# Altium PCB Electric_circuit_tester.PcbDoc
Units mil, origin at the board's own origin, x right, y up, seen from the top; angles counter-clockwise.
Board outline 6043.31 x 4149.61 mil, 2 copper layers (Top Layer, Top, Bottom Layer, Bottom); 15 components, 10 nets, 34 pads, 0 vias.
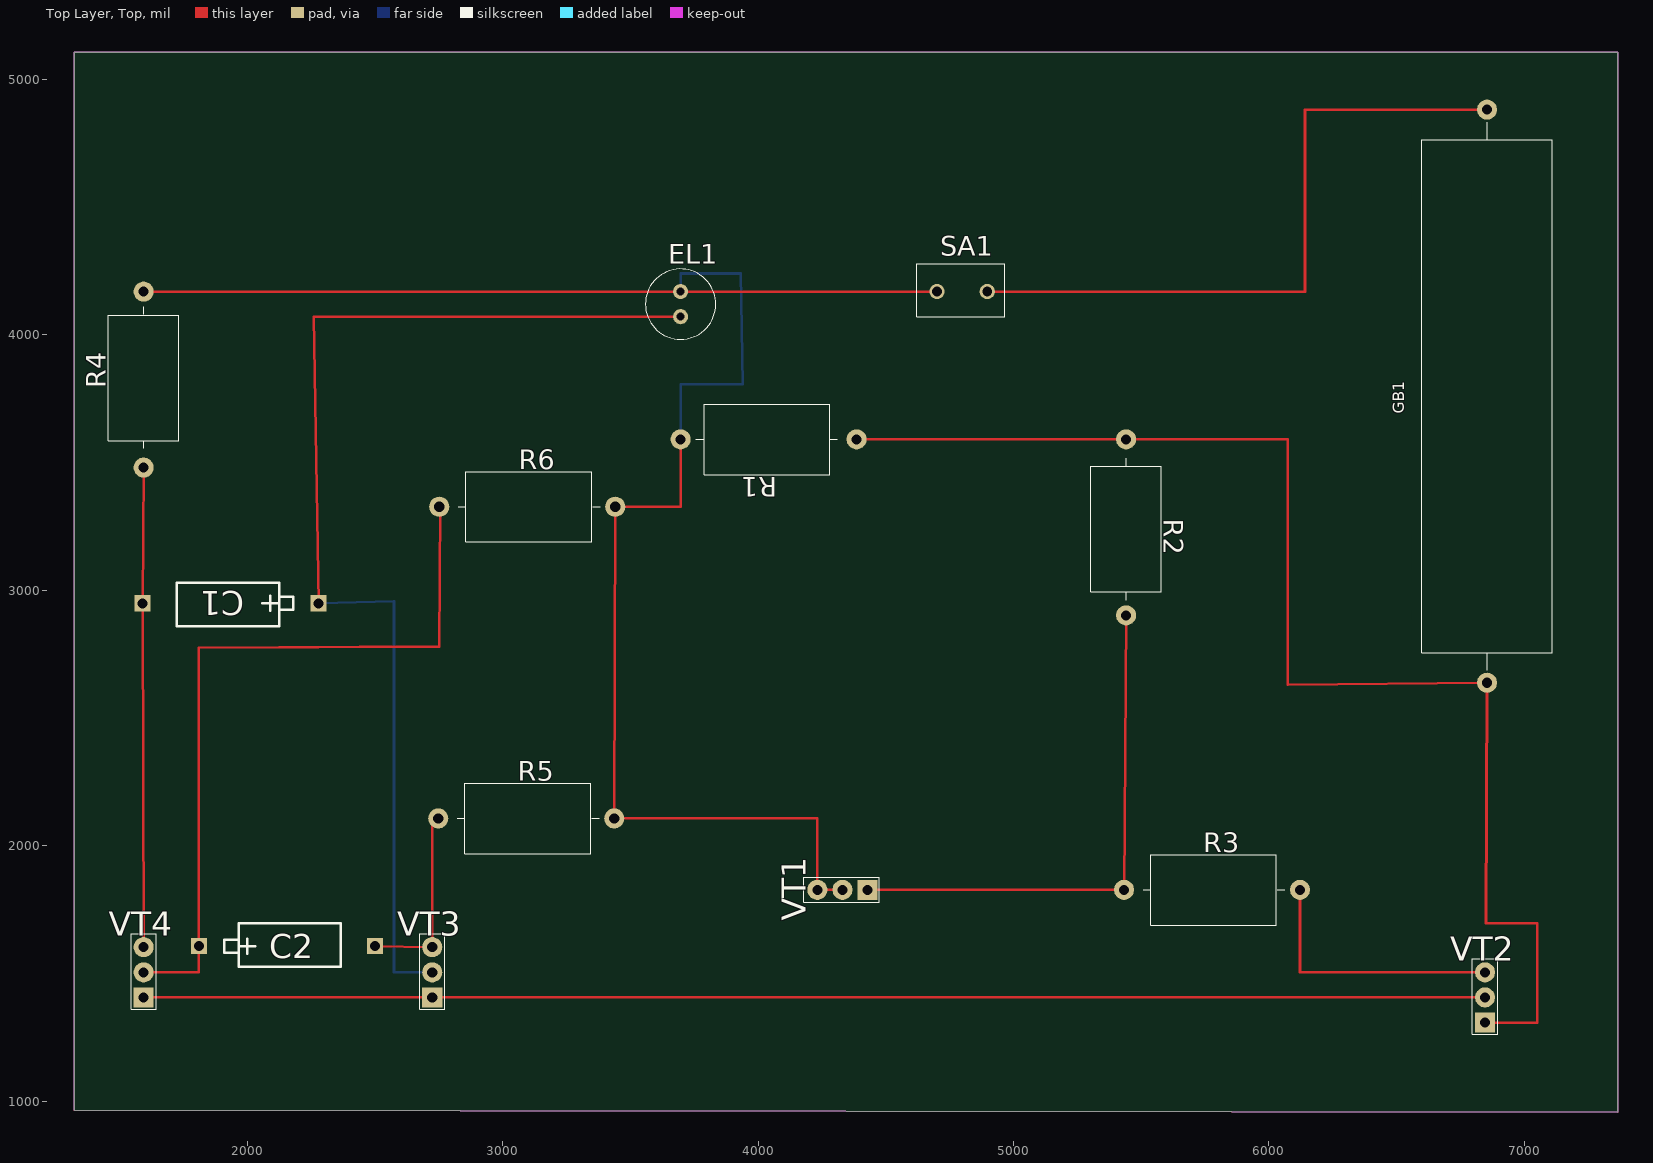
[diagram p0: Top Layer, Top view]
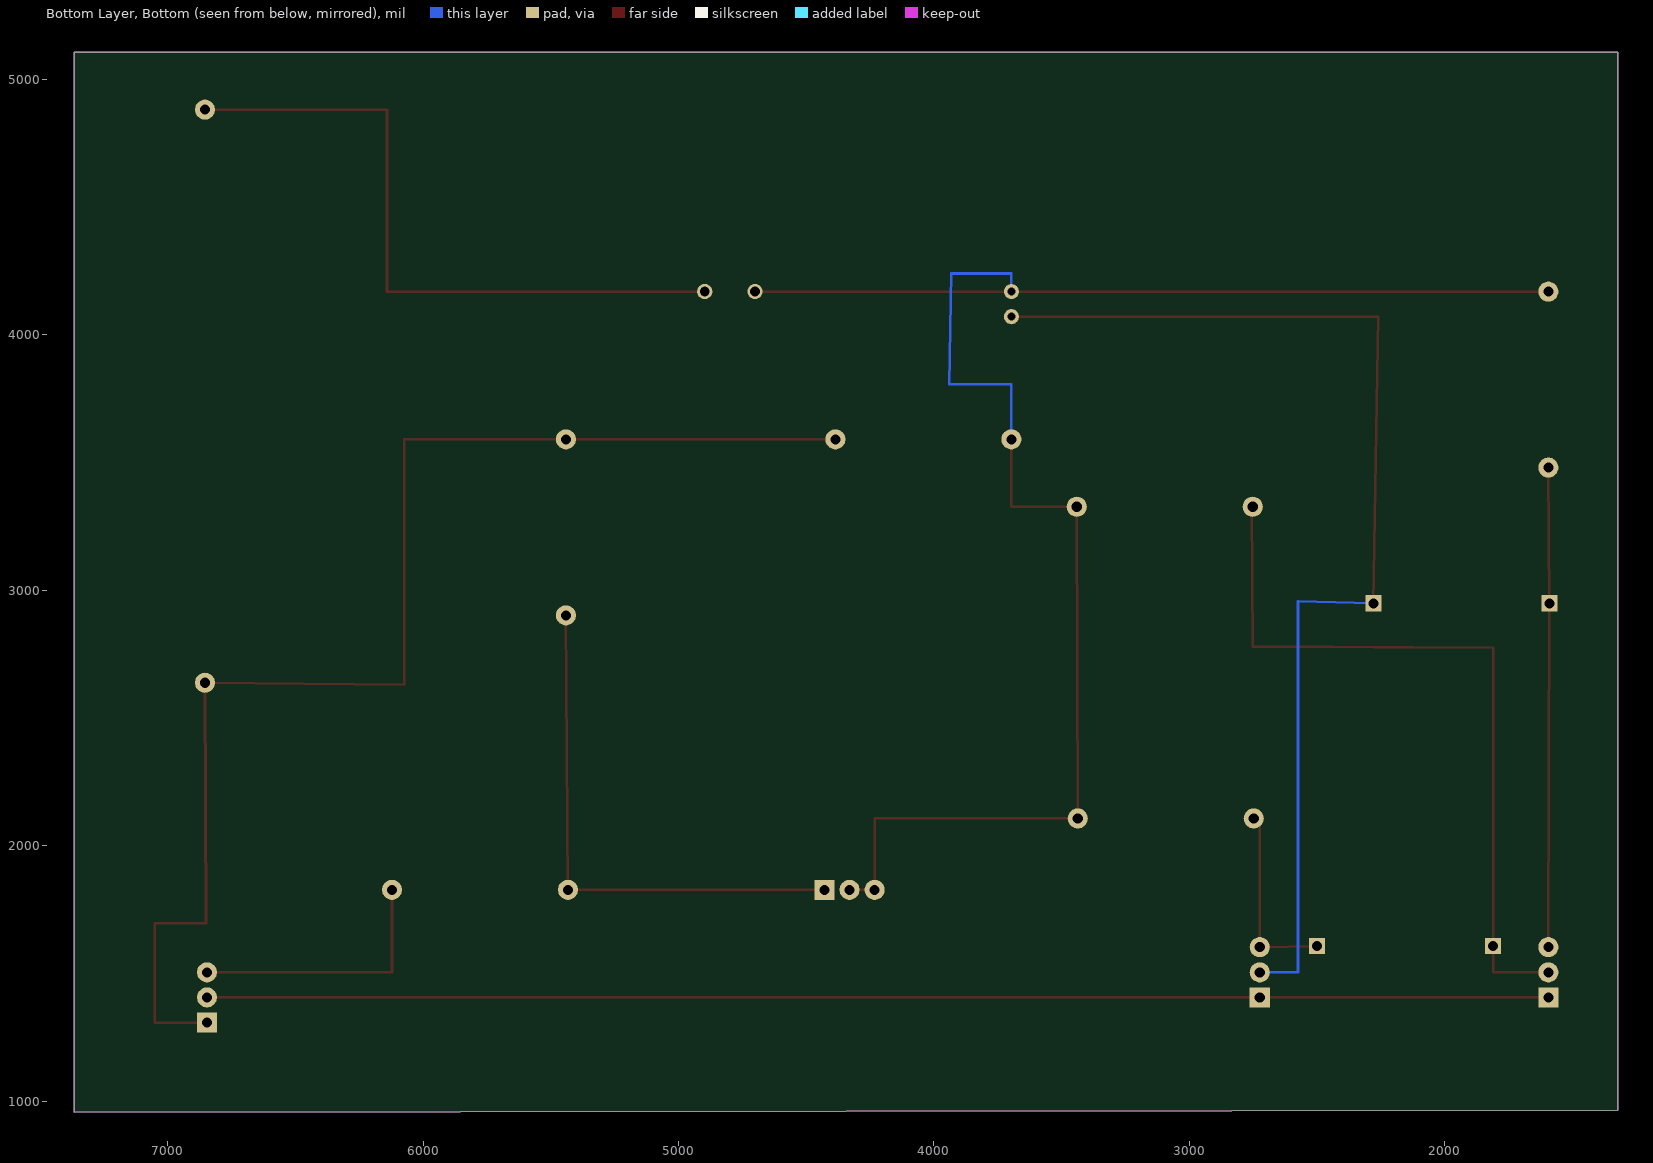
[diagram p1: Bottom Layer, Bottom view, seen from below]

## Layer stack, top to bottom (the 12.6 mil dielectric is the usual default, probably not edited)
Top Solder, Top Mask: solder mask 0.4, Solder Resist, Dk 3.5
Top Layer, Top: signal copper 1.4
Dielectric 1: dielectric 12.6, FR-4, Dk 4.8
Bottom Layer, Bottom: signal copper 1.4
Bottom Solder, Bot Mask: solder mask 0.4, Solder Resist, Dk 3.5

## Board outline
7366.14,956.69 7366.14,5106.3 1322.83,5106.3 1322.83,964.57

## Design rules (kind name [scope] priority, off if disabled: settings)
Clearance [All] p1: gap=10 ignorepadtopadclearanceinfootprint=FALSE except(0: Arc-Hole Track-Hole SMDPad-Hole THPad-Hole Via-Hole Fill-Hole Poly-Hole Region-Hole Text-Hole; 11.81: Arc-Arc Arc-Track Arc-THPad Arc-Via Track-Track Track-THPad Track-Via THPad-THPad THPad-Via Via-Via)
PlaneClearance [All] p1: clearance=10
PolygonConnect [All] p1: connectstyle=Relief reliefconductorwidth=10 reliefentries=4 polygonreliefangle="90 Angle" airgapwidth=10
RoutingVias [All] p1: holewidth=28 width=50 viastyle="Through Hole" minholewidth=28 minwidth=50 maxholewidth=28 maxwidth=50
SolderMaskExpansion [All] p1: expansion=4 istentingtop=FALSE
Width [All] p1: maxlimit=10 minlimit=10 preferedwidth=10
29 further rules are at their usual default settings.

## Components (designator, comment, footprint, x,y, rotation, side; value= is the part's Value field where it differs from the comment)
C1 "6,8mk x 10B" K534A-2 2279.53,2948.82 r180 top
C2 "6,8mk x 10B" K534A-2 1811.02,1606.3 r0 top
EL1 "{Value}" HL_MINI 3696.85,4070.87 r0 top
GB1 "9B" "BH-624 (1X AAA)" 6854.33,3759.84 r90 top
R1 "47k" C2-33H-1W_17.5MM 4385.83,3590.55 r180 top
R2 "8,2k" C2-33H-1W_17.5MM 5440.94,3590.55 r270 top
R3 "1,2k" C2-33H-1W_17.5MM 5433.07,1826.77 r0 top
R4 "33 k" C2-33H-1W_17.5MM 1594.49,3480.32 r90 top
R5 "33k" C2-33H-1W_17.5MM 2748.03,2106.3 r0 top
R6 "8,2k" C2-33H-1W_17.5MM 2751.97,3326.77 r0 top
SA1 "" 8AS9M2RE 4700.79,4169.29 r0 top
VT1 "" KT13_КТ315Б(Primary) 4429.13,1826.77 r90 top
VT2 "" KT13_КТ315Б(Primary) 6846.46,1307.09 r0 top
VT3 "" KT13_КТ315Б(Primary) 2724.41,1405.51 r0 top
VT4 "" KT13_КТ315Б(Primary) 1594.49,1405.51 r0 top

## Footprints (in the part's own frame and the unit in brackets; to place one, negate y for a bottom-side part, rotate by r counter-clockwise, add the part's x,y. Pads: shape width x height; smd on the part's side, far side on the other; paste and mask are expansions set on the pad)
8AS9M2RE [mil]
  round 60 hole 38: 1(0,0) 2(196.85,0)
  silkscreen extent -79,-98 266,108
"BH-624 (1X AAA)" [mm]
  round 2 hole 1: 1(-28.5,0) 2(28.5,0)
  silkscreen extent -27.25,-6.5 27.25,6.5
C2-33H-1W_17.5MM [mm]
  round 2 hole 1: 1(0,0) 2(17.5,0)
  silkscreen extent 1.9,-3.5 16,3.5
HL_MINI [mm]
  round 1.5 hole 0.8: 1(0,0) 2(0,2.5)
  silkscreen extent -3.5,-2.25 3.5,4.75
K534A-2 [mm]
  rect 1.6x1.6 hole 1: 1(0,0) 2(17.5,0)
  silkscreen extent 2.54,-2.03 14.1,2.29
KT13_КТ315Б(Primary) [mm]
  rect 2x2 hole 1: 1(0,0)
  round 2 hole 1: 2(0,5) 3(0,2.5)
  silkscreen extent -1.25,-1.17 1.25,6.33

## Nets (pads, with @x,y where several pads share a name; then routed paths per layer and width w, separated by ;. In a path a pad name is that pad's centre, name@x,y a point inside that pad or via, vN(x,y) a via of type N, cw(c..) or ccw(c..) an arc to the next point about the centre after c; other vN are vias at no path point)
+12B: EL1.2 R1.2 R4.2 R5.2 R6.2 SA1.1 VT1.2 VT1.3 | length 7220.6
  Top Layer, Top w10: R4.2 EL1.2 SA1.1 ; R1.2 3696.85,3326.77 R6.2 R5.2 4232.28,2106.3 VT1.2 VT1.3
  Bottom Layer, Bottom w10: R1.2 3696.85,3807.09 3940.94,3807.09 3933.07,4240.16 3696.85,4240.16 EL1.2
NET00001: GB1.1 R1.1 R2.1 VT2.1 | length 5165.4
  Top Layer, Top w10: R1.1 R2.1 6074.8,3590.55 6074.8,2629.92 GB1.1 6850.39,1696.85 7051.18,1696.85 7051.18,1307.09 VT2.1
NET00003: R2.2 R3.1 VT1.1 | length 2078.8
  Top Layer, Top w10: VT1.1 R3.1 R2.2
NET00005: GB1.2 SA1.2 | length 2669.3
  Top Layer, Top w10: SA1.2 6141.73,4169.29 6141.73,4881.89 GB1.2
NET00006: R3.2 VT2.2 | length 1047.2
  Top Layer, Top w10: R3.2 6122.05,1503.94 VT2.2
NET00007: VT2.3 VT3.1 VT4.1 | length 5252
  Top Layer, Top w10: VT4.1 VT3.1 VT2.3
NET00008: C1.1 EL1.1 VT3.3 | length 4457
  Top Layer, Top w10: C1.1 2259.84,4070.87 EL1.1
  Bottom Layer, Bottom w10: C1.1 2574.8,2956.69 2574.8,1503.94 VT3.3
NET00010: C2.2 R5.1 VT3.2 | length 752
  Top Layer, Top w10: C2.2 VT3.2 2724.41,2106.3 R5.1
NET00011: C1.2 R4.1 VT4.2 | length 1885.8
  Top Layer, Top w10: VT4.2 C1.2@1590.56,2947.32 ; R4.1 C1.2@1590.56,2947.32 ; C1.2@1590.56,2947.32 C1.2 1590.55,2944.88 C1.2@1590.56,2947.32
NET00013: C2.1 R6.1 VT4.3 | length 2980.3
  Top Layer, Top w10: VT4.3 1811.02,1503.94 C2.1 1811.02,2775.59 2751.97,2779.53 2755.91,3326.77 R6.1

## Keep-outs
Keep-Out Layer, Board:
  the board outline again, w5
